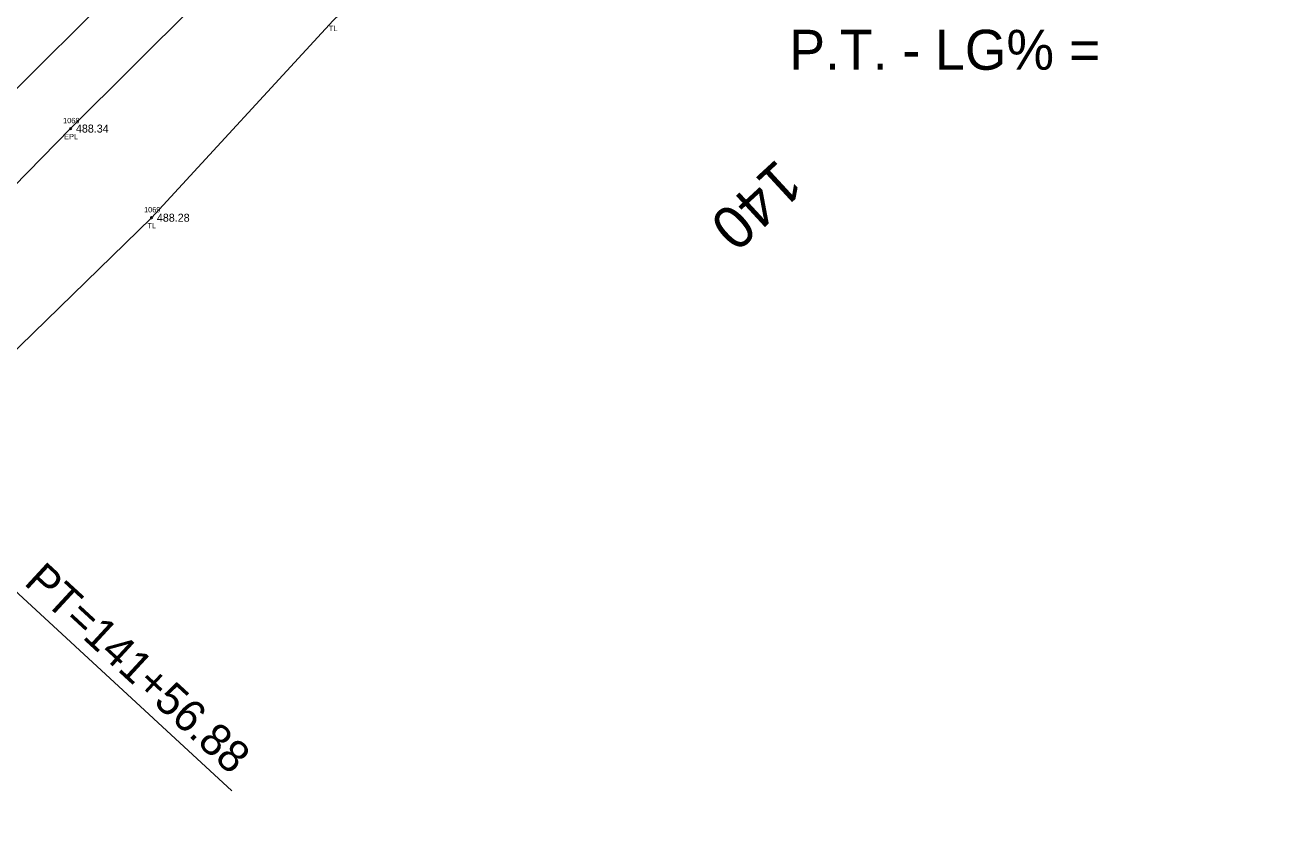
# Model space of a CAD drawing. Extents: x 1740701 to 1743138, y 748181 to 751839.
# Drawn here: x 1741947.8 to 1742183.5, y 750307.2 to 750456.4 of the extents above; entities that cross this region are included whole.
import ezdxf

# ---------------------------------------------------------------- set-up
doc = ezdxf.new("R2010")
doc.units = 0
for name, color, linetype in [('RD_EX_Road', 7, 'Continuous'), ('RD_EX_Road_txCode', 7, 'Continuous'), ('RD_EX_TX_Road_ELEV', 7, 'Continuous'), ('RD_EX_TX_VEG_ELEV', 7, 'Continuous'), ('RD_EX_VEG', 7, 'Continuous'), ('RD_EX_VEG_txCode', 7, 'Continuous'), ('RD_HC_Cl', 7, 'Continuous'), ('RD_HC_Data', 7, 'Continuous'), ('RD_HC_TX_Sta50', 7, 'Continuous'), ('RD_SMD_Locator', 7, 'Continuous')]:
    doc.layers.add(name, color=color, linetype=linetype)

msp = doc.modelspace()

# ---------------------------------------------------------------- linework, layer by layer
at = {"layer": 'RD_EX_Road'}
msp.add_lwpolyline([(1742102.43, 750570.61), (1742093.26, 750562.71), (1742064.72, 750538.42), (1742027.92, 750505.65), (1741991.25, 750471.83), (1741956.32, 750436.98), (1741921.43, 750401.39), (1741886.79, 750364.93), (1741819.64, 750292.67), (1741751.78, 750219.01), (1741684.42, 750145.59), (1741650.98, 750108.5), (1741637.17, 750092.42), (1741621.17, 750073.94), (1741621.31, 750072.22), (1741619.24, 750070.27)], dxfattribs=at)
at = {"layer": 'RD_EX_VEG'}
msp.add_lwpolyline([(1742114.37, 750556.95), (1742102.57, 750548.5), (1742074.74, 750526.88), (1742042.48, 750492.43), (1742005.49, 750457.25), (1741971.49, 750420.27), (1741936.96, 750386.65), (1741902.94, 750350.76), (1741835.15, 750278.46), (1741766.69, 750206.43), (1741693.82, 750135.64), (1741661.95, 750096.11), (1741631.51, 750044.18), (1741602.3, 750028.04), (1741573.25, 749982.32), (1741544.84, 749941.06), (1741514.68, 749901.47), (1741495.89, 749858.02), (1741462.75, 749819.18), (1741434.73, 749775.9), (1741408.39, 749735.06), (1741355.53, 749651.67)], dxfattribs=at)
at = {"layer": 'RD_HC_Cl'}
msp.add_arc((1743302.33, 749099.61), 1909.86, 121.38831, 137.32219, dxfattribs=at)
at = {"layer": 'RD_HC_Data'}
msp.add_line((1741898.25, 750394.26), (1741986.56, 750312.83), dxfattribs=at)
at = {"layer": 'RD_SMD_Locator'}
for centre in [(1741956.32, 750436.98), (1741971.49, 750420.27)]:
    msp.add_circle(centre, 0.15, dxfattribs=at)

# ---------------------------------------------------------------- texts
at = {"layer": 'RD_EX_Road_txCode'}
for s, p in [('1068', (1741954.91, 750437.98)), ('EPL', (1741955.11, 750434.98))]:
    msp.add_text(s, height=1, dxfattribs=at).set_placement(p)
at = {"layer": 'RD_EX_TX_Road_ELEV'}
msp.add_text('488.34', height=1.5, dxfattribs=at).set_placement((1741957.32, 750436.23))
at = {"layer": 'RD_EX_TX_VEG_ELEV'}
msp.add_text('488.28', height=1.5, dxfattribs=at).set_placement((1741972.49, 750419.52))
at = {"layer": 'RD_EX_VEG_txCode'}
for s, p in [('TL', (1742004.72, 750455.25)), ('1069', (1741970.08, 750421.27)), ('TL', (1741970.71, 750418.27))]:
    msp.add_text(s, height=1, dxfattribs=at).set_placement(p)
at = {"layer": 'RD_HC_Data'}
msp.add_text('P.T. - LG% = ', height=7.5, dxfattribs=at).set_placement((1742091, 750448))
msp.add_text('PT=141+56.88', height=6, rotation=317.3222, dxfattribs=at).set_placement((1741947.39, 750351.67))
at = {"layer": 'RD_HC_TX_Sta50'}
msp.add_text('140', height=8, rotation=222.6157, dxfattribs=at).set_placement((1742088.76, 750431.54))

doc.saveas('drawing.dxf')
